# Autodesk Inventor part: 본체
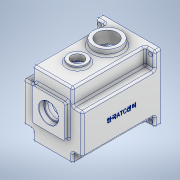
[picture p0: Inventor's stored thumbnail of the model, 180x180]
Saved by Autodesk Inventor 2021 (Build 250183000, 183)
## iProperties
Created: 2022-08
Part Number: 본체
Material: 알루미늄 6061
Document SubType Name: Modeling
Designer: Owner
Density: 2.7 g/cm^3
Appearance: 알루미늄 - 평지
Mass: 1407.52 g
Surface Area: 1166.43 cm^2
Volume: 521.305 cm^3
Author: Owner
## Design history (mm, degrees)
sketch "스케치1"
  geometry: L1 (-49, -55)-(49, -55); L2 (49, -55)-(49, 55); L3 (49, 55)-(-49, 55); L4 (-49, 55)-(-49, -55); L5 (-49, -55)-(49, 55); L6 (49, -55)-(-49, 55); 1 further point
  constraints: 12 end point, 2 midpoint, 2 parallel, 1 horizontal, 1 perpendicular
  dimensions: "d0" = 98 distance of L2.end L3.end; "d1" = 110 distance of L3.end L1.start
extrude "돌출1" new body sketch "스케치1" distance "d2" = 130; taper "d3" = 0 deg
sketch "스케치2"
  geometry: L1 (49, 55)-(-49, 55) reference; L2 (-49, 55)-(-33, 55); L3 (-33, 55)-(-33, 28); L4 (-33, 28)-(-49, 28); L5 (-49, 28)-(-49, 55); 2 further points
  constraints: 8 end point, 2 parallel, 1 horizontal, 1 perpendicular
  dimensions: "d4" = 27 distance of L4.end L1.end; "d5" = 16 distance of L3.end L4.end
extrude "돌출2" cut sketch "스케치2" distance "d6" = 120; taper "d7" = 0 deg
sketch "스케치3"
  geometry: L1 (-49, -55)-(49, -55) reference; L2 (-49, -55)-(-33, -55); L3 (-33, -55)-(-33, -38); L4 (-33, -38)-(-49, -38); L5 (-49, -38)-(-49, -55); 2 further points
  constraints: 8 end point, 2 parallel, 1 horizontal, 1 perpendicular
  dimensions: "d8" = 17 distance of L4.end L1.start; "d9" = 16 distance of L3.end L4.end
extrude "돌출3" cut sketch "스케치3" distance "d10" = 120; taper "d11" = 0 deg
sketch "스케치4"
  geometry: L1 (98, 0)-(0, 0) reference; C1 r 15 at (49, -89); 2 further points
  constraints: 1 centre point, 1 midpoint, 1 vertical alignment
  dimensions: "d12" = 30 diameter of C1; "d13" = 89 distance of point (49, 0) C1.centre
extrude "돌출4" join sketch "스케치4" distance "d14" = 5; taper "d15" = 0 deg
sketch "스케치5"
  geometry: L1 (98, 0)-(0, 0) reference; C1 r 22.5 at (49, -40); 2 further points
  constraints: 1 centre point, 1 midpoint, 1 vertical alignment
  dimensions: "d16" = 40 distance of point (49, 0) C1.centre; "d17" = 45 diameter of C1
extrude "돌출5" join sketch "스케치5" distance "d18" = 10; taper "d19" = 0 deg
sketch "스케치6"
  geometry: L1 (-27, 33)-(27, 33); L2 (27, 33)-(27, -21); L3 (27, -21)-(-27, -21); L4 (-27, -21)-(-27, 33); L5 (-27, 33)-(27, -21); L6 (27, 33)-(-27, -21); L7 (-33, -55)-(33, -55) reference; 3 further points
  constraints: 12 end point, 3 midpoint, 2 parallel, 1 horizontal, 1 perpendicular, 1 vertical alignment
  dimensions: "d20" = 54 distance of L1.start L1.end; "d21" = 54 distance of L1.end L2.end; "d39" = 61 distance from line of L7 point (0, 6)
sketch "스케치7"
  geometry: L1 (49, -55)-(-49, -55) reference; L2 (-23, 45)-(23, 45); L3 (-23, 45)-(-23, 30.143); L4 (0, -79)-(0, 89) reference; L5 (23, 45)-(23, 30.143); L6 (-26, 31.729)-(-26, 48); L7 (-26, 48)-(26, 48); L8 (26, 48)-(26, 31.729); A1 r 42 centre (0, -5) between (-23, 30.143) and (23, 30.143); A2 r 45 centre (0, -5) between (-26, 31.729) and (26, 31.729); 1 further point
  constraints: 12 end point, 4 point on circle, 2 centre point, 2 symmetric about line, 1 horizontal, 1 vertical, 1 vertical alignment, 3 other
  dimensions: "d22" = 50 distance from line of L1 A1.centre; "d23" = 84 diameter of A1; "d24" = 50 distance from line of A1.centre L2; "d25" = 23 distance from line of point (0, 0) L3; "d26" = 3 radial gap between concentric circles of A1 A2
extrude "돌출6" cut sketch "스케치7" distance "d27" = 9; taper "d28" = 0 deg
sketch "스케치8"
  geometry: L1 (23, 30.143)-(23, 45) reference; L2 (23, 45)-(-23, 45) reference; L3 (-23, 45)-(-23, 30.143) reference; L4 (-82.202, -5)-(83.378, -5); L5 (0, -71.333)-(0, 75.392); L6 (-35.777, -1)-(-41.809, -1); L7 (-35.777, -9)-(-41.809, -9); L8 (35.777, -1)-(41.809, -1); L9 (35.777, -9)-(41.809, -9); A1 r 42 centre (0, -5) between (-23, 30.143) and (23, 30.143) reference; A2 r 42 centre (0, -5) between (-23, 30.143) and (23, 30.143) reference; A3 r 36 centre (0, -5) between (-36, -5) and (-35.777, -1); A4 r 4 centre (-36, -5) between (-36, -9) and (-36, -1); A5 r 4 centre (36, -5) between (36, -1) and (36, -9); 9 further points
  constraints: 12 end point, 9 point on circle, 9 symmetric about line, 7 point on line, 3 centre point, 2 horizontal, 2 tangent, 1 coincident, 1 parallel, 1 vertical, 1 other
  dimensions: "d29" = 72 diameter of A3; "d30" = 8 diameter of A4
extrude "돌출7" cut sketch "스케치8" distance "d31" = 114; taper "d32" = 0 deg
sketch "스케치9"
  geometry: L1 (-68.808, -5)-(75.827, -5); L2 (-68.808, 6)-(75.827, 6); L3 (0, -92.071)-(0, 86.583); L4 (-36, -1)-(-41.809, -1) reference; L5 (-41.809, -9)-(-36, -9) reference; L6 (36, -9)-(41.809, -9) reference; L7 (41.809, -1)-(36, -1) reference; L8 (23, 45)-(23, 30.143) reference; L9 (-23, 45)-(23, 45) reference; L10 (-23, 30.143)-(-23, 45) reference; A1 r 42 centre (0, -5) between (-41.809, -9) and (41.809, -9) reference; A2 r 21 centre (0, 6) between (8.978, -12.984) and (-8.978, -12.984); A3 r 15 centre (0, -25) between (-8.978, -12.984) and (8.978, -12.984); A4 r 42 centre (0, -5) between (-23, 30.143) and (-41.809, -1) reference; A5 r 4 centre (-36, -5) between (-36, -9) and (-36, -1) reference; A6 r 42 centre (0, -5) between (-41.809, -9) and (41.809, -9) reference; A7 r 4 centre (36, -5) between (36, -1) and (36, -9) reference; A8 r 42 centre (0, -5) between (41.809, -1) and (23, 30.143) reference; 3 further points
  constraints: 6 end point, 5 point on line, 4 point on circle, 2 centre point, 1 horizontal, 1 parallel, 1 vertical
  dimensions: "d33" = 11 distance between parallel lines of L1 L2; "d34" = 42 diameter of A2; "d35" = 30 diameter of A3; "d36" = 20 distance of A1.centre A3.centre
extrude "돌출8" cut sketch "스케치9" distance "d37" = 7; taper "d38" = 0 deg
extrude "돌출9" join sketch "스케치6" distance "d40" = 7; taper "d41" = 0 deg
sketch "스케치10"
  geometry: L1 (-33, -55)-(33, -55) reference; 2 further points
  constraints: 1 vertical alignment
  dimensions: "d42" = 61 distance from line of L1 point (0, 6)
hole "구멍1" sketch "스케치10" at (0, 6) diameter "d43" = 28; stored, may be unused: countersink angle "d47" = 90 deg, drill point angle "d49" = 0 deg; dims "d44" = 8, "d45" = 32, "d46" = 8.3, "d48" = 40
sketch "스케치11"
  geometry: C1 r 14 at (0, 6) reference; C2 r 17.5 at (0, 6); 1 further point
  constraints: 1 centre point, 1 coincident
  dimensions: "d50" = 35 diameter of C2
extrude "돌출10" cut sketch "스케치11" distance "d51" = 10; taper "d52" = 0 deg
sketch "스케치12"
  geometry: A1 r 15 centre (0, -25) between (-8.978, -12.984) and (8.978, -12.984) reference; 2 further points
  constraints: 1 coincident
hole "구멍2" sketch "스케치12" at (0, -25) diameter "d53" = 19; stored, may be unused: countersink angle "d57" = 90 deg, drill point angle "d59" = 0 deg; dims "d54" = 8, "d55" = 22, "d56" = 7, "d58" = 10
sketch "스케치13"
  geometry: C1 r 15 at (23, 80) reference; 2 further points
  constraints: 1 coincident
hole "구멍3" sketch "스케치13" at (23, 80) diameter "d60" = 20; stored, may be unused: countersink angle "d64" = 90 deg, drill point angle "d66" = 0 deg; dims "d61" = 8, "d62" = 30, "d63" = 5, "d65" = 10
sketch "스케치14"
  geometry: C1 r 22.5 at (0, 0) reference; 2 further points
  constraints: 1 coincident
hole "구멍4" sketch "스케치14" at (0, 0) diameter "d67" = 33.376; stored, may be unused: countersink angle "d71" = 90 deg, drill point angle "d73" = 0 deg; dims "d68" = 70, "d69" = 19.05, "d70" = 4.775, "d72" = 10
sketch "스케치15"
  geometry: A1 r 4 centre (-36, -5) between (-36, -9) and (-36, -1) reference; 2 further points
  constraints: 1 coincident
hole "구멍5" sketch "스케치15" at (-36, -5) diameter "d74" = 3.242; stored, may be unused: countersink angle "d78" = 90 deg, drill point angle "d80" = 118 deg; dims "d75" = 7, "d76" = 19.05, "d77" = 4.775, "d79" = 9
fillet "모깎기1" dims "d81" = 0.3
fillet "모깎기2" dims "d82" = 0.3
fillet "모깎기3" dims "d83" = 0.3
fillet "모깎기5" dims "d85" = 3
fillet "모깎기6" dims "d86" = 3
fillet "모깎기7" dims "d87" = 3
fillet "모깎기8" dims "d88" = 3
fillet "모깎기9" dims "d89" = 3
fillet "모깎기10" dims "d90" = 3
fillet "모깎기11" dims "d91" = 3
fillet "모깎기12" dims "d92" = 3
fillet "모깎기13" dims "d93" = 3
fillet "모깎기14" dims "d94" = 3
fillet "모깎기15" dims "d95" = 3
fillet "모깎기17" dims "d97" = 6
fillet "모깎기18" dims "d98" = 3
fillet "모깎기19" dims "d99" = 3
chamfer "모따기1" distance "d100" = 0.8; stored, may be unused: second distance "d101" = 2, angle "d102" = 30 deg
chamfer "모따기2" distance "d103" = 1; stored, may be unused: second distance "d104" = 2, angle "d105" = 30 deg
chamfer "모따기3" distance "d106" = 1; stored, may be unused: second distance "d107" = 2, angle "d108" = 30 deg
sketch "스케치16"
  geometry: L1 (-130, 104)-(-130, 83) reference; L2 (-13, 107)-(-127, 107) reference; 2 further points
  constraints: 1 other
  dimensions: "d113" = 65 distance from line of L1 point (-65, 47); "d114" = 60 distance from line of L2 point (-65, 47)
feature "엠보싱1" sketch "스케치16" dims "d115" = 0.5, "d116" = 0
sketch "스케치17"
  geometry: L1 (41.809, -1)-(38.367, -1) reference; L2 (38.367, -9)-(41.809, -9) reference; L3 (-41.809, -9)-(-38.367, -9) reference; L4 (-38.367, -1)-(-41.809, -1) reference; L5 (-23, 42)-(-23, 33.249) reference; L6 (20, 45)-(-20, 45) reference; L7 (23, 33.249)-(23, 42) reference; L8 (-26, 48)-(26, 48) reference; L9 (-26, 31.729)-(-26, 48) reference; L10 (26, 48)-(26, 31.729) reference; L11 (-36, -1)-(-41.809, -1) reference; L12 (-41.809, -9)-(-36, -9) reference; L13 (36, -9)-(41.809, -9) reference; L14 (41.809, -1)-(36, -1) reference; A1 r 45 centre (0, -5) between (-26, 31.729) and (26, 31.729) reference; A2 r 6 centre (29, 33.249) between (23, 33.249) and (25.375, 28.468) reference; A3 r 42 centre (0, -5) between (41.318, 2.538) and (25.375, 28.468) reference; A4 r 3 centre (38.367, 2) between (38.367, -1) and (41.318, 2.538) reference; A5 r 42 centre (0, -5) between (41.809, -9) and (41.809, -1) reference; A6 r 3 centre (38.367, -12) between (41.318, -12.538) and (38.367, -9) reference; A7 r 42 centre (0, -5) between (-41.318, -12.538) and (41.318, -12.538) reference; A8 r 3 centre (-38.367, -12) between (-38.367, -9) and (-41.318, -12.538) reference; A9 r 42 centre (0, -5) between (-41.809, -1) and (-41.809, -9) reference; A10 r 3 centre (-38.367, 2) between (-41.318, 2.538) and (-38.367, -1) reference; A11 r 42 centre (0, -5) between (-25.375, 28.468) and (-41.318, 2.538) reference; A12 r 6 centre (-29, 33.249) between (-25.375, 28.468) and (-23, 33.249) reference; A13 r 3 centre (-20, 42) between (-20, 45) and (-23, 42) reference; A14 r 3 centre (20, 42) between (23, 42) and (20, 45) reference; A15 r 45 centre (0, -5) between (-26, 31.729) and (26, 31.729) reference; A16 r 4 centre (-36, -5) between (-36, -9) and (-36, -1) reference; A17 r 4 centre (36, -5) between (36, -1) and (36, -9) reference; 3 further points
extrude "돌출11" cut sketch "스케치17" distance "d117" = 10; taper "d118" = 0 deg
fillet "모깎기21" dims "d119" = 3
chamfer "모따기5" distance "d120" = 1; stored, may be unused: second distance "d121" = 2, angle "d122" = 30 deg
sketch "스케치18"
  geometry: L1 (-49, -52)-(-49, 52) reference; L2 (-46, 55)-(46, 55) reference; 2 further points
  dimensions: "d123" = 7 distance from line of point (-42, 48) L1; "d124" = 7 distance from line of L2 point (-42, 48)
hole "구멍6" sketch "스케치18" at (-42, 48) diameter "d125" = 7; stored, may be unused: countersink angle "d129" = 90 deg, drill point angle "d131" = 118 deg; dims "d126" = 7, "d127" = 19.05, "d128" = 4.775, "d130" = 9
node "솔리드1"
mirror "미러1"
mirror "미러2"
mirror "미러3"
mirror "미러4"
mirror "미러5"
node "투영된 루프1"
node "투영된 루프2"
node "투영된 루프3"
feature "A9D066F2-1C7D-4E18-AEED-F7BC21143FA4" dims "d43" = 28, "d44" = 8, "d45" = 32, "d46" = 8.3, "d47" = 90 deg, "d48" = 40, "d49" = 0
